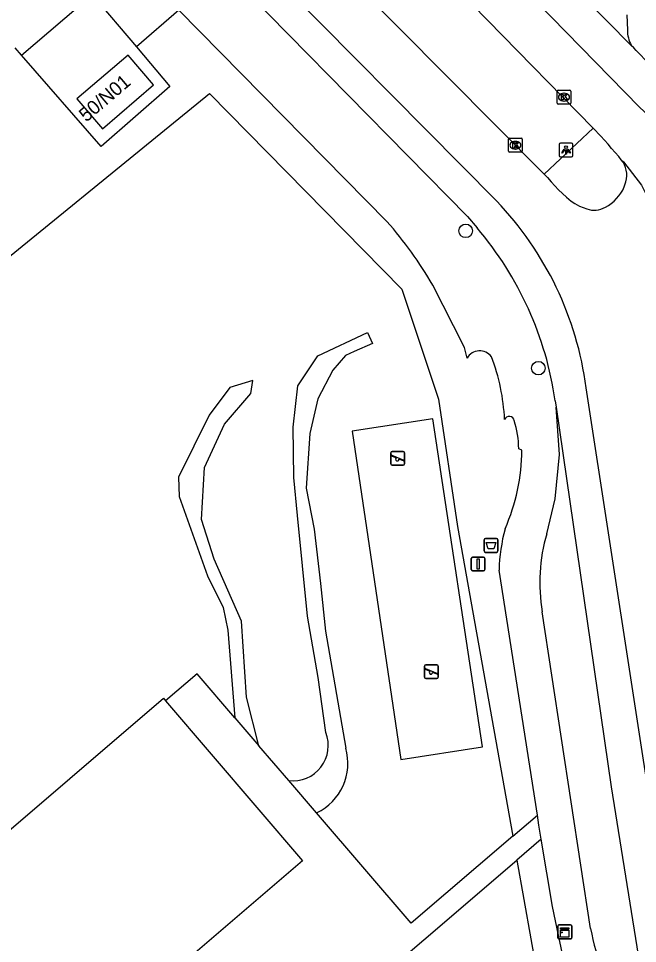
# Model space of a CAD drawing. Extents: x 158474 to 159560, y 388525 to 389605.
# Drawn here: x 159182.5 to 159227.2, y 389012.4 to 389079.1 of the extents above; entities that cross this region are included whole.
import ezdxf

# ---------------------------------------------------------------- set-up
doc = ezdxf.new("R2010")
doc.units = 0
for name, color, linetype in [('IMGEO_Afvalbak', 7, 'Continuous'), ('IMGEO_Boom', 7, 'Continuous'), ('IMGEO_Groenvoorziening', 7, 'Continuous'), ('IMGEO_Kast', 7, 'Continuous'), ('IMGEO_Kolk', 7, 'Continuous'), ('IMGEO_Lichtpunt', 7, 'Continuous'), ('IMGEO_Pand', 7, 'Continuous'), ('IMGEO_Pand_nummerreeks', 7, 'Continuous'), ('IMGEO_Rijbaan_lokaal_gesloten', 7, 'Continuous'), ('IMGEO_Rijbaan_lokaal_open', 7, 'Continuous'), ('IMGEO_Speelvoorziening', 7, 'Continuous'), ('IMGEO_Verkeersbordpaal', 7, 'Continuous'), ('IMGEO_Verkeerseiland_groen', 7, 'Continuous'), ('IMGEO_Voetpad_gesloten', 7, 'Continuous'), ('IMGEO_Voetpad_open', 7, 'Continuous')]:
    doc.layers.add(name, color=color, linetype=linetype)

msp = doc.modelspace()

# ---------------------------------------------------------------- linework, layer by layer
at = {"layer": 'IMGEO_Afvalbak'}
for p, q in [((159216.107, 389040.688), (159216.107, 389041.488)), ((159216.107, 389041.488), (159216.107, 389040.688)), ((159216.207, 389041.588), (159216.997, 389041.588)), ((159216.997, 389041.588), (159216.207, 389041.588)), ((159217.097, 389041.488), (159217.097, 389040.688)), ((159217.097, 389040.688), (159217.097, 389041.488)), ((159216.997, 389040.588), (159216.207, 389040.588)), ((159216.207, 389040.588), (159216.997, 389040.588))]:
    msp.add_line(p, q, dxfattribs=at)
msp.add_lwpolyline([(159216.25, 389041.302), (159216.954, 389041.302), (159216.805, 389040.832), (159216.399, 389040.832), (159216.25, 389041.302)], dxfattribs=at)
for centre, start, end in [((159216.207, 389041.488), 90, 180), ((159216.207, 389041.488), 90, 180), ((159216.997, 389041.488), 0, 90), ((159216.997, 389041.488), 360, 90), ((159216.207, 389040.688), 180, 270), ((159216.207, 389040.688), 180, 270), ((159216.997, 389040.688), 270, 0), ((159216.997, 389040.688), 270, 0)]:
    msp.add_arc(centre, 0.1, start, end, dxfattribs=at)
at = {"layer": 'IMGEO_Boom'}
for centre in [(159214.783, 389063.758), (159220.024, 389053.861)]:
    msp.add_circle(centre, 0.489, dxfattribs=at)
at = {"layer": 'IMGEO_Groenvoorziening'}
for points in [[(159172.865, 389012.863), (159163.799, 389047.245), (159177.696, 389058.53), (159196.313, 389073.65), (159210.179, 389059.558), (159212.821, 389051.632), (159214.2, 389042.452), (159218.174, 389020.125)], [(159204.692, 389027.598), (159204.132, 389031.555), (159203.369, 389035.976), (159202.643, 389043.244), (159202.394, 389045.977), (159202.328, 389049.614), (159202.68, 389052.596), (159204.127, 389054.746), (159207.707, 389056.426), (159208.062, 389055.637), (159206.738, 389055.072), (159206.102, 389054.782), (159205.206, 389053.727), (159204.104, 389051.664), (159203.529, 389049.145), (159203.279, 389045.21), (159203.854, 389042.247), (159204.301, 389038.342), (159204.67, 389034.911), (159206.125, 389026.485)], [(159199.862, 389026.653), (159198.96, 389030.154), (159198.6, 389035.619), (159196.636, 389040.102), (159195.713, 389042.95), (159195.944, 389046.713), (159197.38, 389049.828), (159199.285, 389052.038), (159199.436, 389052.974), (159197.764, 389052.464), (159196.281, 389050.486), (159194.075, 389046.008), (159194.107, 389044.602), (159196.163, 389038.904), (159197.293, 389036.618), (159197.629, 389034.977), (159198.136, 389028.662)], [(159218.479, 389018.411), (159226.051, 388975.866), (159227.164, 388969.613), (159186.891, 388959.671), (159183.615, 388972.096)]]:
    msp.add_lwpolyline(points, dxfattribs=at)
for centre, radius, start, end in [((159202.32, 389026.667), 2.548, 263.29796, 21.44179), ((159202.337, 389025.373), 3.948, 295.31626, 16.35962)]:
    msp.add_arc(centre, radius, start, end, dxfattribs=at)
at = {"layer": 'IMGEO_Kast'}
for p, q in [((159221.427, 389012.806), (159221.427, 389013.647)), ((159221.427, 389013.647), (159221.427, 389012.806)), ((159221.502, 389013.731), (159222.343, 389013.731)), ((159222.343, 389013.731), (159221.502, 389013.731)), ((159222.427, 389013.656), (159222.427, 389012.815)), ((159222.427, 389012.815), (159222.427, 389013.656)), ((159222.352, 389012.731), (159221.511, 389012.731)), ((159221.511, 389012.731), (159222.352, 389012.731))]:
    msp.add_line(p, q, dxfattribs=at)
for points in [[(159221.622, 389013.521), (159222.222, 389013.521), (159222.222, 389013.436), (159221.622, 389013.436), (159221.622, 389013.521)], [(159221.622, 389013.346), (159222.222, 389013.346), (159222.222, 389012.857), (159221.622, 389012.857), (159221.622, 389013.346)]]:
    msp.add_lwpolyline(points, dxfattribs=at)
msp.add_circle((159221.706, 389013.195), 0.0377, dxfattribs=at)
for centre, start, end in [((159221.505, 389013.653), 92.4484, 184.28452), ((159221.505, 389013.653), 92.4484, 184.28452), ((159222.349, 389013.653), 2.4484, 94.28452), ((159222.349, 389013.653), 2.4484, 94.28452), ((159221.505, 389012.809), 182.4484, 274.28452), ((159221.505, 389012.809), 182.4484, 274.28452), ((159222.349, 389012.809), 272.4484, 4.28452), ((159222.349, 389012.809), 272.4484, 4.28452)]:
    msp.add_arc(centre, 0.0779, start, end, dxfattribs=at)
at = {"layer": 'IMGEO_Kolk'}
for p, q in [((159221.368, 389072.967), (159221.368, 389073.819)), ((159221.443, 389073.893), (159222.295, 389073.893)), ((159221.856, 389073.673), (159221.881, 389073.673)), ((159222.369, 389073.819), (159222.369, 389072.967)), ((159221.879, 389073.113), (159221.854, 389073.113)), ((159222.295, 389072.893), (159221.443, 389072.893)), ((159217.862, 389069.505), (159217.862, 389070.357)), ((159217.937, 389070.431), (159218.789, 389070.431)), ((159218.863, 389070.357), (159218.863, 389069.505)), ((159218.373, 389069.651), (159218.348, 389069.651)), ((159218.35, 389070.211), (159218.375, 389070.211)), ((159218.789, 389069.431), (159217.937, 389069.431))]:
    msp.add_line(p, q, dxfattribs=at)
for points in [[(159221.368, 389072.967), (159221.368, 389073.819)], [(159221.443, 389073.893), (159222.295, 389073.893)], [(159222.369, 389073.819), (159222.369, 389072.967)], [(159221.689, 389073.593), (159221.812, 389073.593), (159221.812, 389073.442), (159221.942, 389073.593), (159222.106, 389073.593), (159221.96, 389073.442), (159222.113, 389073.193), (159221.961, 389073.193), (159221.876, 389073.357), (159221.812, 389073.29), (159221.812, 389073.193), (159221.689, 389073.193), (159221.689, 389073.593)], [(159222.295, 389072.893), (159221.443, 389072.893)], [(159217.862, 389069.505), (159217.862, 389070.357)], [(159217.937, 389070.431), (159218.789, 389070.431)], [(159218.863, 389070.357), (159218.863, 389069.505)], [(159218.183, 389070.131), (159218.306, 389070.131), (159218.306, 389069.98), (159218.436, 389070.131), (159218.6, 389070.131), (159218.454, 389069.98), (159218.607, 389069.731), (159218.455, 389069.731), (159218.37, 389069.895), (159218.306, 389069.828), (159218.306, 389069.731), (159218.183, 389069.731), (159218.183, 389070.131)], [(159218.789, 389069.431), (159217.937, 389069.431)]]:
    msp.add_lwpolyline(points, dxfattribs=at)
for centre, start, end in [((159221.445, 389073.817), 91.55205, 178.44795), ((159221.445, 389073.817), 91.55205, 178.44795), ((159222.293, 389073.817), 1.55205, 88.44795), ((159222.293, 389073.817), 1.55205, 88.44795), ((159221.445, 389072.969), 181.55205, 268.44795), ((159221.445, 389072.969), 181.55205, 268.44795), ((159222.293, 389072.969), 271.55205, 358.44795), ((159222.293, 389072.969), 271.55205, 358.44795), ((159217.939, 389070.355), 91.55205, 178.44795), ((159217.939, 389070.355), 91.55205, 178.44795), ((159218.787, 389070.355), 1.55205, 88.44795), ((159218.787, 389070.355), 1.55205, 88.44795), ((159217.939, 389069.507), 181.55205, 268.44795), ((159217.939, 389069.507), 181.55205, 268.44795), ((159218.787, 389069.507), 271.55205, 358.44795), ((159218.787, 389069.507), 271.55205, 358.44795)]:
    msp.add_arc(centre, 0.0765, start, end, dxfattribs=at)
for centre, major_axis, ratio, start_param, end_param in [((159221.855, 389073.393), (-0.387, 0.002), 0.722429, 4.712389, 7.853982), ((159221.88, 389073.393), (-0.39, 0.002), 0.717154, 1.570796, 4.712389), ((159218.349, 389069.931), (-0.387, 0.002), 0.722429, 4.712389, 7.853982), ((159218.374, 389069.931), (-0.39, 0.002), 0.717154, 1.570796, 4.712389)]:
    msp.add_ellipse(centre, major_axis=major_axis, ratio=ratio, start_param=start_param, end_param=end_param, dxfattribs=at)
at = {"layer": 'IMGEO_Lichtpunt'}
for p, q in [((159221.516, 389069.986), (159221.516, 389069.179)), ((159221.516, 389069.986), (159221.516, 389069.179)), ((159222.418, 389070.081), (159221.61, 389070.081)), ((159222.418, 389070.081), (159221.61, 389070.081)), ((159222.512, 389069.179), (159222.512, 389069.986)), ((159222.512, 389069.179), (159222.512, 389069.986)), ((159221.61, 389069.085), (159222.418, 389069.085)), ((159221.61, 389069.085), (159222.418, 389069.085))]:
    msp.add_line(p, q, dxfattribs=at)
for points in [[(159221.89, 389069.65), (159221.929, 389069.622), (159221.741, 389069.36), (159221.703, 389069.387), (159221.89, 389069.65)], [(159222.102, 389069.622), (159222.14, 389069.649), (159222.327, 389069.387), (159222.288, 389069.359), (159222.102, 389069.622)], [(159221.992, 389069.602), (159222.039, 389069.602), (159222.039, 389069.28), (159221.992, 389069.28), (159221.992, 389069.602)]]:
    msp.add_lwpolyline(points, dxfattribs=at)
msp.add_circle((159222.015, 389069.784), 0.0994, dxfattribs=at)
for centre, start, end in [((159221.61, 389069.986), 90, 180), ((159221.61, 389069.986), 90, 180), ((159222.418, 389069.986), 0, 90), ((159222.418, 389069.986), 0, 90), ((159221.61, 389069.179), 180, 270), ((159221.61, 389069.179), 180, 270), ((159222.418, 389069.179), 270, 0), ((159222.418, 389069.179), 270, 360)]:
    msp.add_arc(centre, 0.0946, start, end, dxfattribs=at)
at = {"layer": 'IMGEO_Pand'}
for points in [[(159188.581, 389071.12), (159192.27, 389074.287), (159190.428, 389076.433), (159186.739, 389073.266), (159188.581, 389071.12)], [(159193.124, 389029.895), (159203.019, 389018.342), (159177.236, 388996.288), (159165.476, 388986.23), (159155.422, 388997.939)], [(159172.865, 389012.863), (159192.975, 389030.069), (159193.124, 389029.895)]]:
    msp.add_lwpolyline(points, dxfattribs=at)
at = {"layer": 'IMGEO_Rijbaan_lokaal_gesloten'}
for points in [[(159226.719, 389077.131), (159211.02, 389093.059)], [(159209.204, 389091.239), (159218.854, 389081.353), (159227.325, 389072.674), (159228.98, 389071.135)], [(159223.964, 389071.159), (159208.737, 389086.754), (159206.77, 389088.8)], [(159202.002, 389086.439), (159202.927, 389085.485), (159220.436, 389067.84)], [(159217.003, 389065.916), (159199.281, 389083.822)], [(159197.699, 389082.3), (159214.91, 389064.804), (159215.602, 389063.967)], [(159231.709, 389072.086), (159231.114, 389072.6), (159230.541, 389073.143), (159229.985, 389073.704), (159229.439, 389074.277), (159229.092, 389074.645), (159228.353, 389075.424), (159227.809, 389075.994), (159227.271, 389076.571), (159227.085, 389076.755), (159226.901, 389076.942), (159226.719, 389077.131)], [(159226.001, 389068.883), (159225.814, 389069.108), (159225.56, 389069.408), (159225.305, 389069.703), (159225.048, 389069.996), (159224.791, 389070.287), (159224.532, 389070.577), (159223.964, 389071.159)], [(159226.001, 389068.883), (159226.154, 389068.732), (159227.448, 389067.049), (159229.363, 389063.258), (159230.694, 389059.225), (159232.111, 389052.733), (159232.143, 389052.454)], [(159220.436, 389067.84), (159220.678, 389067.596), (159220.939, 389067.301), (159221.203, 389067.009), (159221.472, 389066.725), (159221.75, 389066.45), (159222.038, 389066.188), (159222.397, 389065.901), (159222.658, 389065.72), (159222.997, 389065.528), (159223.513, 389065.336)], [(159226.22, 389066.925), (159226.334, 389067.299)], [(159268.084, 388832.358), (159258.627, 388872.238), (159243.098, 388939.791), (159230.156, 389009.067), (159223.469, 389052.45)], [(159221.236, 389051.504), (159221.3, 389051.06)], [(159221.3, 389051.06), (159225.262, 389023.694), (159228.791, 389001.832)]]:
    msp.add_lwpolyline(points, dxfattribs=at)
for centre, radius, start, end in [((159224.659, 389067.774), 1.741, 344.17227, 39.57223), ((159223.343, 389068.242), 3.164, 298.5666, 335.40561), ((159199.667, 389049.306), 24.009, 7.52378, 43.77428), ((159224.042, 389066.906), 1.657, 251.38094, 299.42321), ((159196.927, 389048.02), 24.558, 8.15661, 40.49486)]:
    msp.add_arc(centre, radius, start, end, dxfattribs=at)
at = {"layer": 'IMGEO_Rijbaan_lokaal_open'}
for points in [[(159220.626, 389041.929), (159221.238, 389044.445), (159221.554, 389047.64), (159221.3, 389051.06)], [(159223.785, 389013.474), (159220.306, 389036.302)]]:
    msp.add_lwpolyline(points, dxfattribs=at)
for centre, radius, start, end in [((159232.482, 389038.432), 12.361, 163.56656, 189.92379), ((159242.466, 389017.054), 19.021, 190.84935, 210.57153)]:
    msp.add_arc(centre, radius, start, end, dxfattribs=at)
at = {"layer": 'IMGEO_Speelvoorziening'}
for p, q in [((159209.384, 389046.962), (159209.384, 389047.762)), ((159209.384, 389047.762), (159209.384, 389046.962)), ((159209.484, 389047.862), (159210.274, 389047.862)), ((159210.274, 389047.862), (159209.484, 389047.862)), ((159210.374, 389047.762), (159210.374, 389046.962)), ((159210.374, 389046.962), (159210.374, 389047.762)), ((159209.767, 389047.39), (159209.428, 389047.527)), ((159209.453, 389047.587), (159210.329, 389047.234)), ((159210.305, 389047.174), (159209.965, 389047.311)), ((159210.274, 389046.862), (159209.484, 389046.862)), ((159209.484, 389046.862), (159210.274, 389046.862)), ((159211.806, 389031.59), (159211.806, 389032.39)), ((159211.806, 389032.39), (159211.806, 389031.59)), ((159211.906, 389032.49), (159212.696, 389032.49)), ((159212.696, 389032.49), (159211.906, 389032.49)), ((159212.796, 389032.39), (159212.796, 389031.59)), ((159212.796, 389031.59), (159212.796, 389032.39)), ((159212.189, 389032.018), (159211.85, 389032.155)), ((159211.875, 389032.215), (159212.751, 389031.862)), ((159212.727, 389031.802), (159212.387, 389031.939)), ((159212.696, 389031.49), (159211.906, 389031.49)), ((159211.906, 389031.49), (159212.696, 389031.49))]:
    msp.add_line(p, q, dxfattribs=at)
for centre, radius, start, end in [((159209.484, 389047.762), 0.1, 90, 180), ((159209.484, 389047.762), 0.1, 90, 180), ((159210.274, 389047.762), 0.1, 0, 90), ((159210.274, 389047.762), 0.1, 360, 90), ((159209.441, 389047.557), 0.0327, 68.07798, 248.07798), ((159209.846, 389047.3), 0.12, 130.99278, 5.16318), ((159210.317, 389047.204), 0.0327, 248.07798, 68.07798), ((159209.484, 389046.962), 0.1, 180, 270), ((159209.484, 389046.962), 0.1, 180, 270), ((159210.274, 389046.962), 0.1, 270, 0), ((159210.274, 389046.962), 0.1, 270, 0), ((159211.906, 389032.39), 0.1, 90, 180), ((159211.906, 389032.39), 0.1, 90, 180), ((159212.696, 389032.39), 0.1, 0, 90), ((159212.696, 389032.39), 0.1, 360, 90), ((159211.863, 389032.185), 0.0327, 68.07798, 248.07798), ((159212.268, 389031.928), 0.12, 130.99278, 5.16318), ((159212.739, 389031.832), 0.0327, 248.07798, 68.07798), ((159211.906, 389031.59), 0.1, 180, 270), ((159211.906, 389031.59), 0.1, 180, 270), ((159212.696, 389031.59), 0.1, 270, 0), ((159212.696, 389031.59), 0.1, 270, 0)]:
    msp.add_arc(centre, radius, start, end, dxfattribs=at)
at = {"layer": 'IMGEO_Verkeersbordpaal'}
for p, q in [((159215.181, 389039.347), (159215.181, 389040.147)), ((159215.181, 389040.147), (159215.181, 389039.347)), ((159215.281, 389040.247), (159216.071, 389040.247)), ((159216.071, 389040.247), (159215.281, 389040.247)), ((159216.171, 389040.147), (159216.171, 389039.347)), ((159216.171, 389039.347), (159216.171, 389040.147)), ((159216.071, 389039.247), (159215.281, 389039.247)), ((159215.281, 389039.247), (159216.071, 389039.247))]:
    msp.add_line(p, q, dxfattribs=at)
msp.add_lwpolyline([(159215.601, 389040.122), (159215.751, 389040.122), (159215.751, 389039.372), (159215.601, 389039.372), (159215.601, 389040.122)], dxfattribs=at)
for centre, start, end in [((159215.281, 389040.147), 90, 180), ((159215.281, 389040.147), 90, 180), ((159216.071, 389040.147), 0, 90), ((159216.071, 389040.147), 360, 90), ((159215.281, 389039.347), 180, 270), ((159215.281, 389039.347), 180, 270), ((159216.071, 389039.347), 270, 0), ((159216.071, 389039.347), 270, 0)]:
    msp.add_arc(centre, 0.1, start, end, dxfattribs=at)
at = {"layer": 'IMGEO_Verkeerseiland_groen'}
msp.add_lwpolyline([(159223.964, 389071.159), (159220.436, 389067.84)], dxfattribs=at)
at = {"layer": 'IMGEO_Voetpad_gesloten'}
msp.add_lwpolyline([(159206.596, 389049.328), (159210.101, 389025.648), (159215.989, 389026.561), (159212.412, 389050.21), (159206.596, 389049.328)], dxfattribs=at)
at = {"layer": 'IMGEO_Voetpad_open'}
for points in [[(159182.754, 389076.416), (159187.84, 389080.797), (159191.028, 389077.034)], [(159209.102, 389064.431), (159194.101, 389079.676), (159191.028, 389077.034)], [(159226.403, 389079.318), (159226.441, 389078.232)], [(159191.028, 389077.034), (159193.438, 389074.174), (159188.482, 389069.831), (159182.754, 389076.416)], [(159182.754, 389076.416), (159182.297, 389076.941)], [(159214.874, 389054.589), (159214.695, 389055.346), (159213.892, 389056.921), (159212.404, 389059.84)], [(159218.836, 389047.959), (159218.605, 389048.049)], [(159219.946, 389021.639), (159217.191, 389039.313)], [(159198.136, 389028.662), (159195.411, 389031.836), (159193.124, 389029.895)], [(159198.136, 389028.662), (159199.862, 389026.653)], [(159202.023, 389024.136), (159199.862, 389026.653)], [(159204.025, 389021.804), (159202.023, 389024.136)], [(159218.174, 389020.125), (159210.843, 389013.865), (159204.025, 389021.804)], [(159218.174, 389020.125), (159219.946, 389021.639)], [(159220.227, 389019.907), (159220.057, 389020.924), (159219.946, 389021.639)], [(159220.227, 389019.907), (159218.479, 389018.411)], [(159230.064, 388970.898), (159229.467, 388973.693), (159228.61, 388978.653), (159227.943, 388978.548), (159225.223, 388994.122), (159224.161, 389000), (159222.498, 389009.21), (159222.011, 389010.48), (159221.036, 389015.051), (159220.227, 389019.907)], [(159198.681, 389001.477), (159211.761, 389012.659), (159218.479, 389018.411)]]:
    msp.add_lwpolyline(points, dxfattribs=at)
for centre, radius, start, end in [((159228.711, 389078.22), 2.27, 179.686, 208.65571), ((159187.88, 389045.685), 28.316, 29.99393, 41.45596), ((159215.79, 389054.046), 1.065, 37.15615, 149.32936), ((159203.147, 389049.518), 14.449, 2.53209, 20.97117), ((159217.923, 389050.017), 0.368, 10.84886, 157.76228), ((159211.883, 389048.033), 6.722, 0.13214, 17.77844), ((159204.522, 389048.062), 14.314, 336.22874, 359.58865), ((159229.415, 389039.065), 12.227, 164.69714, 178.83807)]:
    msp.add_arc(centre, radius, start, end, dxfattribs=at)

# ---------------------------------------------------------------- texts
at = {"layer": 'IMGEO_Pand_nummerreeks'}
msp.add_text('50/N01', height=1, rotation=40.38935, dxfattribs=at).set_placement((159187.417, 389071.559))

doc.saveas('drawing.dxf')
